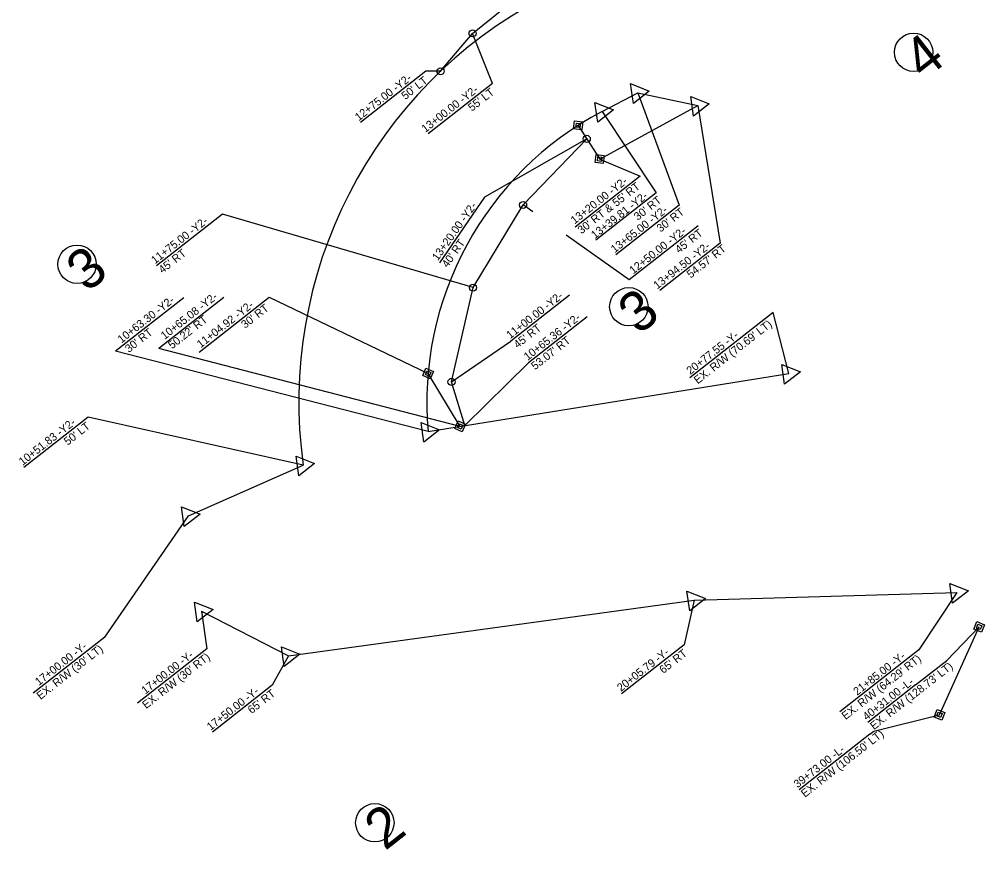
# Model space of a CAD drawing. Extents: x 2175623 to 2194100, y 76458 to 87202.
# Drawn here: x 2175739 to 2176343, y 77181 to 77699 of the extents above; entities that cross this region are included whole.
import ezdxf

# ---------------------------------------------------------------- set-up
doc = ezdxf.new("R2010")
doc.units = 0
for name, color, linetype in [('Exist Plan Preparation Drainage Flow Arrows', 7, 'Continuous'), ('Exist Property Iron Pin CELL', 7, 'Continuous'), ('Prop Drainage Structure Box Number Symbol CELL', 7, 'Continuous'), ('Prop Drainage Structure Drop Inlet Grate 840 16 CELL', 7, 'Continuous'), ('Prop Drainage Structure Headwall CELL', 7, 'Continuous'), ('Prop Drainage Structure Pipe RCP 36in Class IV', 7, 'Continuous'), ('Prop Drainage Structure Plot Symbol 20 Scale', 7, 'Continuous'), ('Prop Drainage Structure Plot Symbol 50 Scale', 7, 'Continuous'), ('Prop Earthen Structure Base Ditch Special Lateral Detail Label', 7, 'Continuous'), ('Prop Erosion Rip Rap Pad at Outlet Label', 7, 'Continuous'), ('Prop Plan Preparation Crest Label', 7, 'Continuous'), ('Prop Plan Preparation Sag', 7, 'Continuous'), ('Prop Plan Preparation Sag Label', 7, 'Continuous')]:
    doc.layers.add(name, color=color, linetype=linetype)

# ---------------------------------------------------------------- blocks, each defined once
blk = doc.blocks.new('ROW Marker Permanent Easement-E')
at = {"layer": 'Prop Earthen Structure Base Ditch Special Lateral Detail Label'}
for points in [[(0, 0.072), (0.072, 0), (0, -0.072), (-0.072, 0)], [(0, 0.036), (0.036, 0), (0, -0.036), (-0.036, 0)]]:
    blk.add_lwpolyline(points, close=True, dxfattribs=at)
at = {"layer": 'Prop Plan Preparation Crest Label'}
blk.add_line((0, 0), (0, 0), dxfattribs=at)

msp = doc.modelspace()

# ---------------------------------------------------------------- linework, layer by layer
at = {"layer": 'Exist Plan Preparation Drainage Flow Arrows'}
for p, q in [((2176102.92, 77641.79), (2176125.2, 77653.52)), ((2176125.2, 77653.52), (2176162.75, 77645.52)), ((2175994.24, 77441.88), (2176219.69, 77478.11)), ((2175844.52, 77389.13), (2175916.17, 77420.84)), ((2176160.38, 77336.55), (2176324.7, 77341.24)), ((2175906.96, 77301.8), (2176160.38, 77336.55)), ((2175852.67, 77329.68), (2175906.96, 77301.8))]:
    msp.add_line(p, q, dxfattribs=at)
for radius, end in [(285, 187.97633), (205, 185.17881)]:
    msp.add_arc((2176198.41, 77460.39), radius, 117.76258, end, dxfattribs=at)
at = {"layer": 'Exist Property Iron Pin CELL'}
for centre, radius in [((2176021.99, 77690.55), 2.2), ((2176021.99, 77690.55), 0.0707), ((2176001.99, 77666.9), 2.2), ((2176001.99, 77666.9), 0.0707), ((2176093.37, 77624.68), 2.2), ((2176093.37, 77624.68), 0.0707), ((2176053.59, 77583.38), 2.2), ((2176053.59, 77583.38), 0.0707), ((2176022.31, 77531.73), 2.2), ((2176022.31, 77531.73), 0.0707), ((2176008.82, 77472.87), 2.2), ((2176008.82, 77472.87), 0.0707)]:
    msp.add_circle(centre, radius, dxfattribs=at)
at = {"layer": 'Prop Drainage Structure Box Number Symbol CELL'}
for p, q in [((2176297.6, 77678.75), (2176297.6, 77678.75)), ((2175774.83, 77546.37), (2175774.83, 77546.37)), ((2176119.63, 77519.83), (2176119.63, 77519.83)), ((2175960.91, 77197.47), (2175960.91, 77197.47))]:
    msp.add_line(p, q, dxfattribs=at)
for centre in [(2176297.6, 77678.75), (2175774.83, 77546.37), (2176119.63, 77519.83), (2175960.91, 77197.47)]:
    msp.add_circle(centre, 12, dxfattribs=at)
at = {"layer": 'Prop Drainage Structure Drop Inlet Grate 840 16 CELL'}
for p, q in [((2176101.45, 77612.04), (2176126.79, 77601.36)), ((2176126.79, 77601.36), (2176086.16, 77569.5)), ((2175866.62, 77525.65), (2175825.93, 77493.75)), ((2175851.04, 77491.5), (2175894.9, 77525.88)), ((2175894.9, 77525.88), (2175994.18, 77478.14)), ((2176014.26, 77445.1), (2175825.93, 77493.75))]:
    msp.add_line(p, q, dxfattribs=at)
at = {"layer": 'Prop Drainage Structure Headwall CELL'}
for p, q in [((2176298.82, 77283.56), (2176268.98, 77260.16)), ((2176270.31, 77252.8), (2176226.07, 77218.12))]:
    msp.add_line(p, q, dxfattribs=at)
for points in [[(2176298.82, 77283.56), (2176318.3, 77298.83), (2176338.53, 77319.8)], [(2176270.31, 77252.8), (2176272.69, 77254.66), (2176313.75, 77264.94)]]:
    msp.add_lwpolyline(points, dxfattribs=at)
at = {"layer": 'Prop Drainage Structure Pipe RCP 36in Class IV'}
for p, q in [((2176034.36, 77659.32), (2176021.99, 77690.55)), ((2175992.78, 77666.88), (2175952.05, 77634.95)), ((2176001.99, 77666.9), (2175992.78, 77666.88)), ((2176034.36, 77659.32), (2175994.2, 77627.84)), ((2176093.37, 77624.68), (2176029.54, 77588.3)), ((2176029.54, 77588.3), (2176001.34, 77547.23)), ((2176059.62, 77579.13), (2176053.59, 77583.38)), ((2175865.74, 77577.62), (2175824.57, 77545.35)), ((2176022.31, 77531.73), (2175865.74, 77577.62)), ((2176162.99, 77570.45), (2176119.9, 77536.67)), ((2176119.9, 77536.67), (2176080.38, 77564.51)), ((2176082.57, 77526.99), (2176046, 77498.32)), ((2176093.52, 77513.5), (2176056.95, 77484.82)), ((2176008.82, 77472.87), (2176046, 77498.32)), ((2176017.08, 77445.55), (2176056.95, 77484.82))]:
    msp.add_line(p, q, dxfattribs=at)
at = {"layer": 'Prop Drainage Structure Plot Symbol 20 Scale'}
for p, q in [((2176101.45, 77612.04), (2176162.75, 77645.52)), ((2176087.98, 77633.1), (2176101.45, 77612.04)), ((2176014.26, 77445.1), (2175994.18, 77478.14))]:
    msp.add_line(p, q, dxfattribs=at)
at = {"layer": 'Prop Drainage Structure Plot Symbol 50 Scale'}
msp.add_line((2176313.75, 77264.94), (2176338.53, 77319.8), dxfattribs=at)
at = {"layer": 'Prop Earthen Structure Base Ditch Special Lateral Detail Label'}
for points in [[(2175995.49, 77474.79), (2175990.83, 77476.83), (2175992.87, 77481.49), (2175997.53, 77479.45)], [(2175994.83, 77476.46), (2175992.5, 77477.48), (2175993.52, 77479.81), (2175995.85, 77478.79)], [(2176015.57, 77441.75), (2176010.91, 77443.79), (2176012.95, 77448.45), (2176017.61, 77446.41)], [(2176014.92, 77443.42), (2176012.58, 77444.44), (2176013.6, 77446.77), (2176015.94, 77445.75)]]:
    msp.add_lwpolyline(points, close=True, dxfattribs=at)
at = {"layer": 'Prop Plan Preparation Crest Label'}
for p, q in [((2176125.2, 77653.52), (2176125.2, 77653.52)), ((2176162.75, 77645.52), (2176162.75, 77645.52)), ((2176102.92, 77641.79), (2176102.92, 77641.79)), ((2175994.18, 77478.14), (2175994.18, 77478.14)), ((2176219.69, 77478.11), (2176219.69, 77478.11)), ((2176014.26, 77445.1), (2176014.26, 77445.1)), ((2175994.24, 77441.88), (2175994.24, 77441.88)), ((2175916.17, 77420.84), (2175916.17, 77420.84)), ((2175844.52, 77389.13), (2175844.52, 77389.13)), ((2176324.7, 77341.24), (2176324.7, 77341.24)), ((2176160.38, 77336.55), (2176160.38, 77336.55)), ((2175852.67, 77329.68), (2175852.67, 77329.68)), ((2175906.96, 77301.8), (2175906.96, 77301.8))]:
    msp.add_line(p, q, dxfattribs=at)
for points in [[(2176122.51, 77646.83), (2176120.76, 77659.19), (2176132.34, 77654.54)], [(2176160.06, 77638.83), (2176158.31, 77651.18), (2176169.89, 77646.54)], [(2176100.22, 77635.1), (2176098.48, 77647.45), (2176110.06, 77642.81)], [(2176217, 77471.42), (2176215.25, 77483.78), (2176226.83, 77479.13)], [(2175991.55, 77435.19), (2175989.8, 77447.55), (2176001.38, 77442.9)], [(2175913.47, 77414.15), (2175911.72, 77426.5), (2175923.3, 77421.86)], [(2175841.82, 77382.44), (2175840.08, 77394.79), (2175851.66, 77390.15)], [(2176322, 77334.55), (2176320.26, 77346.91), (2176331.84, 77342.27)], [(2176157.68, 77329.86), (2176155.94, 77342.22), (2176167.52, 77337.57)], [(2175849.97, 77322.99), (2175848.23, 77335.35), (2175859.81, 77330.71)], [(2175904.26, 77295.11), (2175902.52, 77307.47), (2175914.1, 77302.82)]]:
    msp.add_lwpolyline(points, close=True, dxfattribs=at)
at = {"layer": 'Prop Plan Preparation Sag'}
for p, q in [((2176125.2, 77653.52), (2176151.16, 77583.28)), ((2176162.75, 77645.52), (2176176.76, 77559.51)), ((2176102.92, 77641.79), (2176136.64, 77590.99)), ((2176136.64, 77590.99), (2176098.92, 77561.42)), ((2176151.16, 77583.28), (2176111.57, 77552.25)), ((2176176.76, 77559.51), (2176138.93, 77529.85)), ((2175841.46, 77525.44), (2175798.84, 77492.02)), ((2176209.85, 77516.17), (2176157.79, 77475.36)), ((2176219.69, 77478.11), (2176209.85, 77516.17)), ((2175994.24, 77441.88), (2175798.84, 77492.02)), ((2175781.75, 77450.92), (2175741.49, 77419.36)), ((2175916.17, 77420.84), (2175781.75, 77450.92)), ((2175792.2, 77313.48), (2175844.52, 77389.13)), ((2176324.7, 77341.24), (2176300.83, 77305.48)), ((2176160.38, 77336.55), (2176154.16, 77308.6)), ((2175852.67, 77329.68), (2175855.96, 77306.21)), ((2175792.2, 77313.48), (2175747.39, 77278.35)), ((2175855.96, 77306.21), (2175812.61, 77272.22)), ((2176154.16, 77308.6), (2176115.11, 77277.99)), ((2176300.83, 77305.48), (2176251.53, 77266.83)), ((2175906.96, 77301.8), (2175896.84, 77283.52)), ((2175896.84, 77283.52), (2175859.37, 77254.15))]:
    msp.add_line(p, q, dxfattribs=at)
at = {"layer": 'Prop Plan Preparation Sag Label'}
for p, q in [((2176021.99, 77690.55), (2176080.7, 77738.06)), ((2176001.99, 77666.9), (2176021.99, 77690.55)), ((2176053.59, 77583.38), (2176093.37, 77624.68)), ((2176022.31, 77531.73), (2176053.59, 77583.38)), ((2176008.82, 77472.87), (2176022.31, 77531.73)), ((2176017.08, 77445.55), (2176008.82, 77472.87))]:
    msp.add_line(p, q, dxfattribs=at)

# ---------------------------------------------------------------- block references
for p, xscale, yscale, rotation in [((2176087.98, 77633.1), 50, 50, -141.9089540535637), ((2176101.45, 77612.04), 50, 50, -141.9089540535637), ((2176338.53, 77319.8), 49.99999999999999, 50.00000000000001, -156.87942851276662), ((2176313.75, 77264.94), 49.99999999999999, 50.00000000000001, -156.87942851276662)]:
    msp.add_blockref('ROW Marker Permanent Easement-E', p, dxfattribs=dict(at, xscale=xscale, yscale=yscale, rotation=rotation))

# ---------------------------------------------------------------- texts
at = {"layer": 'Prop Drainage Structure Drop Inlet Grate 840 16 CELL'}
for s, p in [('13+20.00 -Y2- ', (2176085.75, 77571.15)), ("30' RT & 55' RT", (2176090.02, 77564.96)), ('10+65.08 -Y2- ', (2175829.55, 77499.02)), ('11+04.92 -Y2- ', (2175852.07, 77493.77)), ("30' RT", (2175879.77, 77505.96)), ("50.22' RT", (2175834.18, 77493.12))]:
    msp.add_text(s, height=5, rotation=38.0951, dxfattribs=at).set_placement(p)
at = {"layer": 'Prop Drainage Structure Headwall CELL'}
for s, p in [("EX. R/W (128.73' LT)", (2176272.84, 77255.25)), ('40+31.00 -L-', (2176268.21, 77261.15)), ("EX. R/W (106.50' LT)", (2176229.67, 77213.05)), ('39+73.00 -L-', (2176225.05, 77218.95))]:
    msp.add_text(s, height=5, rotation=38.0951, dxfattribs=at).set_placement(p)
at = {"layer": 'Prop Drainage Structure Pipe RCP 36in Class IV'}
for s, rotation, p in [('12+75.00 -Y2- ', 38.0951, (2175950.84, 77635.56)), ("50' LT", 38.0951, (2175979.95, 77648.85)), ('13+00.00 -Y2- ', 38.0951, (2175992.46, 77628.29)), ("55' LT", 38.0951, (2176021.58, 77641.58)), ('13+20.00 -Y2- ', 54.6321, (2176000.24, 77548.2)), ('11+75.00 -Y2- ', 38.0951, (2175823.54, 77546.24)), ('12+50.00 -Y2- ', 38.0951, (2176122.38, 77539.95)), ("45' RT", 38.0951, (2176151.03, 77552.88)), ("40' RT", 54.6321, (2176006.35, 77543.85)), ("45' RT", 38.0951, (2175828.17, 77540.33)), ('11+00.00 -Y2- ', 38.0951, (2176045.45, 77499.48)), ("45' RT", 38.0951, (2176050.08, 77493.57)), ('10+65.36 -Y2- ', 38.0951, (2176056.4, 77485.98)), ("53.07' RT", 38.0951, (2176061.03, 77480.08))]:
    msp.add_text(s, height=5, rotation=rotation, dxfattribs=at).set_placement(p)
at = {"layer": 'Prop Erosion Rip Rap Pad at Outlet Label'}
for s, p in [('4', (2176304.02, 77660.98)), ('3', (2175780.95, 77528.36)), ('3', (2176125.75, 77501.82)), ('2', (2175967.27, 77179.65))]:
    msp.add_text(s, height=25, rotation=38.0951, dxfattribs=at).set_placement(p)
at = {"layer": 'Prop Plan Preparation Sag'}
for s, p in [('13+39.81 -Y2- ', (2176098.43, 77561.99)), ("30' RT", (2176125.19, 77573.44)), ("30' RT", (2176139.45, 77566.08)), ('13+65.00 -Y2- ', (2176110.8, 77553.15)), ('13+94.50 -Y2- ', (2176137.42, 77530.53)), ("54.57' RT", (2176158.28, 77537.36)), ('10+63.30 -Y2- ', (2175802.58, 77496.76)), ("EX. R/W (70.69' LT)", (2176162.71, 77471.27)), ("30' RT", (2175807.21, 77490.85)), ('20+77.55 -Y- ', (2176158.08, 77477.17)), ('10+51.83 -Y2- ', (2175740.83, 77420.41)), ("50' LT", (2175769, 77432.97)), ('17+00.00 -Y- ', (2175750.97, 77282.88)), ("EX. R/W (30' LT)", (2175751.96, 77274.13)), ('17+00.00 -Y- ', (2175817.45, 77277.49)), ('20+05.79 -Y- ', (2176114.7, 77279.14)), ("65' RT", (2176141.18, 77290.37)), ("EX. R/W (30' RT)", (2175817.98, 77268.38)), ("EX. R/W (64.29' RT)", (2176255.07, 77261.55)), ('21+85.00 -Y- ', (2176262.32, 77276.76)), ('17+50.00 -Y- ', (2175858.32, 77254.8)), ("65' RT", (2175883.86, 77265.29))]:
    msp.add_text(s, height=5, rotation=38.0951, dxfattribs=at).set_placement(p)

doc.saveas('drawing.dxf')
